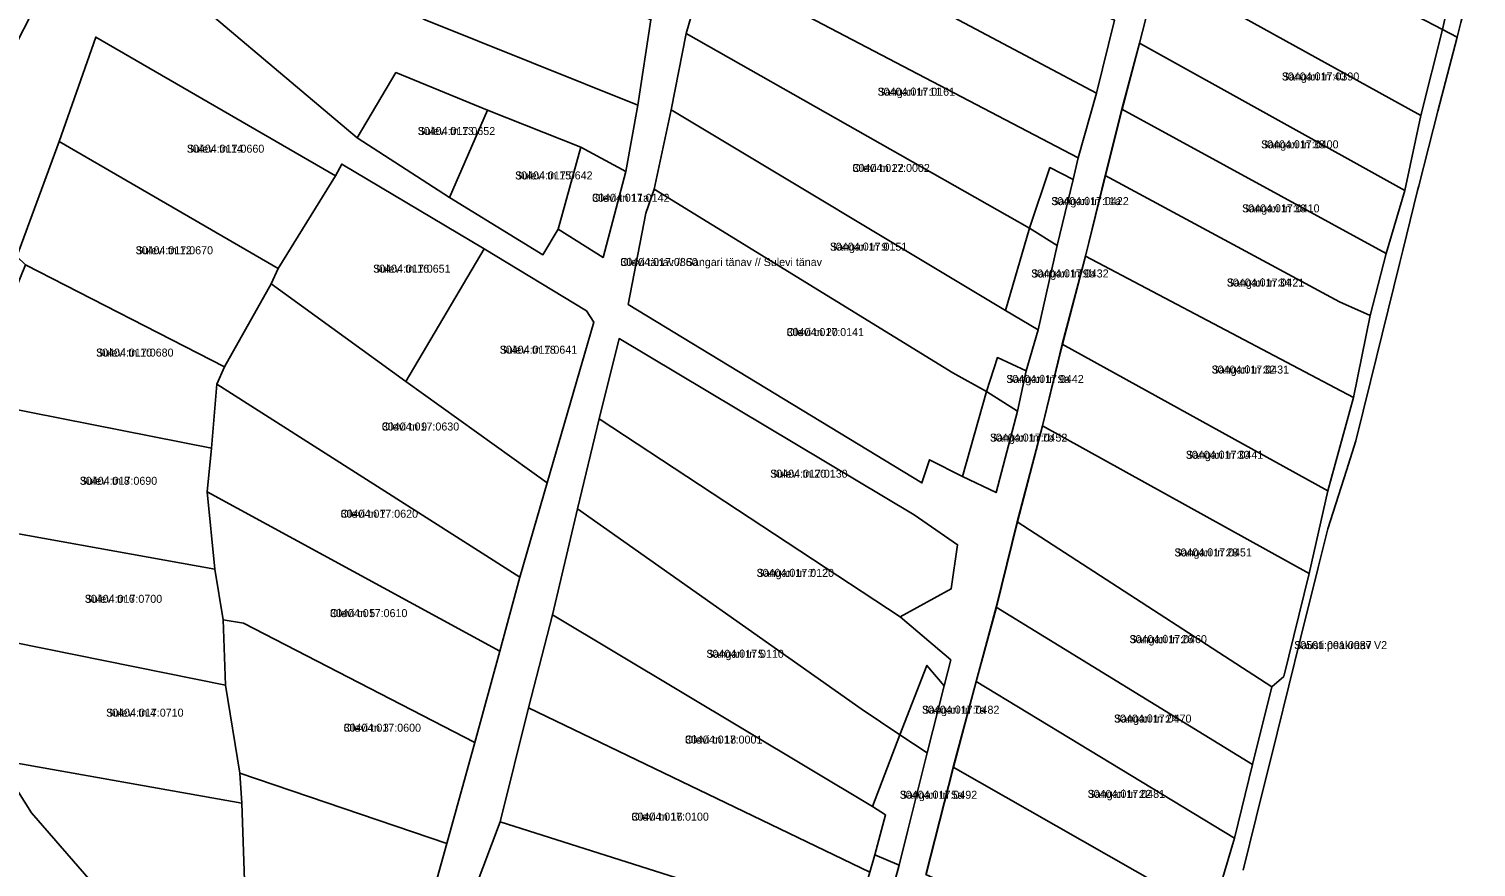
# Model space of a CAD drawing. Extents: x 542681 to 554572, y 6566489 to 6580482.
# Drawn here: x 544141.3 to 544412.6, y 6575830.3 to 6575987.4 of the extents above; entities that cross this region are included whole.
import ezdxf

# ---------------------------------------------------------------- set-up
doc = ezdxf.new("R2010")
doc.units = 0
for name, color, linetype in [('L_AADRESS', 7, 'Continuous'), ('PIIR', 7, 'Continuous'), ('TUNNUS', 7, 'Continuous')]:
    doc.layers.add(name, color=color, linetype=linetype)

msp = doc.modelspace()

# ---------------------------------------------------------------- linework, layer by layer
at = {"layer": 'PIIR'}
for points in [[(544132.71, 6575972.4), (544147.93, 6576002.3), (544147.47, 6576005.67), (544162.57, 6576001.02), (544202.83, 6575966.95), (544220.16, 6575955.78), (544237.67, 6575945.07), (544240.53, 6575949.86), (544248.94, 6575944.56), (544253.22, 6575960.63), (544255.42, 6575973.07), (544257.89, 6575989.06), (544259.46, 6576004.22), (544262.15, 6576022.75), (544264.4, 6576039.1), (544269.25, 6576064.08), (544276.88, 6576081.78), (544276.23, 6576102.8), (544232.03, 6576141.72), (544233.74, 6576145.65), (544276.06, 6576107.08), (544280.65, 6576140.9), (544291.75, 6576177.06)], [(544381.29, 6576166.31), (544393.77, 6576159.4), (544388.82, 6576138.6), (544384.78, 6576123.23), (544380.38, 6576105.94), (544376.63, 6576091.46), (544373.49, 6576078.95), (544370.21, 6576066.27), (544367.09, 6576054.03), (544363.21, 6576038.91), (544359.68, 6576024.81), (544356.57, 6576013.09), (544353, 6575998.36), (544349.5, 6575984.69), (544346.24, 6575972.34), (544343.11, 6575959.91), (544339.38, 6575944.78), (544335.04, 6575928.31), (544331.32, 6575913.02), (544326.6, 6575895.05), (544322.67, 6575879.05), (544318.89, 6575865.14), (544314.59, 6575849.07), (544309.48, 6575828.97)], [(544268.29, 6575999.66), (544264.52, 6575986.52), (544261.72, 6575972.19), (544258.49, 6575957.33), (544256.94, 6575952.84), (544253.66, 6575935.75), (544308.69, 6575902.31), (544310.14, 6575906.66), (544316.31, 6575903.53), (544322.6, 6575900.5), (544326.58, 6575915.74), (544328.21, 6575923.34), (544330.47, 6575931), (544334.01, 6575946.8), (544337.03, 6575959.16), (544337.96, 6575963.2), (544341.42, 6575975.31), (544344.79, 6575988.99)], [(544363.04, 6575821.48), (544367.27, 6575835.78), (544370.64, 6575849.55), (544374.28, 6575864.08), (544376.53, 6575866.05), (544381.27, 6575885.35), (544384.74, 6575900.84), (544389.59, 6575918.31), (544392.71, 6575933.67), (544395.69, 6575945.3), (544399.2, 6575957.07), (544402.23, 6575971.12), (544406.24, 6575987.27), (544409, 6575985.84), (544405.41, 6575971.95), (544403.63, 6575965.06), (544401.8, 6575957.99), (544401.56, 6575957.07), (544398.8, 6575945.86), (544398.24, 6575943.58), (544392.78, 6575921.34), (544390.04, 6575910.2), (544388.24, 6575904.61), (544384.75, 6575893.74), (544382.95, 6575886.48), (544379.65, 6575873.14), (544375.27, 6575855.46), (544371.34, 6575839.62), (544368.9, 6575829.76)], [(544368.9, 6575829.76), (544371.34, 6575839.62), (544375.27, 6575855.46), (544379.65, 6575873.14), (544382.95, 6575886.48), (544384.75, 6575893.74), (544388.24, 6575904.61), (544390.04, 6575910.2), (544392.78, 6575921.34), (544398.24, 6575943.58), (544398.8, 6575945.86), (544401.56, 6575957.07), (544401.8, 6575957.99), (544403.63, 6575965.06), (544405.41, 6575971.95), (544409, 6575985.84), (544409.71, 6575988.58)], [(544209.01, 6575796.68), (544219.68, 6575834.73), (544224.92, 6575853.69), (544229.59, 6575870.78), (544233.34, 6575884.68), (544238.44, 6575902.3), (544247.19, 6575932.44), (544245.8, 6575934.54), (544226.63, 6575946.16), (544199.95, 6575962.06), (544198.79, 6575959.82), (544153.86, 6575985.85), (544146.98, 6575966.27), (544139.03, 6575944.72), (544140.69, 6575943.15), (544130.3, 6575917.75), (544125.43, 6575895.3), (544125.04, 6575889.43), (544127.11, 6575874.75), (544128.58, 6575868.91), (544135.53, 6575850.42), (544141.79, 6575840.51), (544155.07, 6575825.29)], [(544300.11, 6575815.01), (544304.43, 6575830.67), (544306.07, 6575837.25), (544309.67, 6575851.73), (544312.89, 6575864.3), (544314.14, 6575869.14), (544304.61, 6575877.24), (544314.19, 6575882.46), (544315.37, 6575890.74), (544307.21, 6575896.36), (544251.95, 6575929.34), (544248.19, 6575914.3), (544244.17, 6575897.43), (544239.46, 6575877.59), (544234.93, 6575860.18), (544229.65, 6575838.82), (544221.69, 6575817.77)]]:
    msp.add_lwpolyline(points, dxfattribs=at)
for points in [[(544177.07, 6576030.33), (544257.89, 6575989.06), (544255.42, 6575973.07), (544215.56, 6575989.04), (544169.12, 6576014.32)], [(544268.31, 6576027.25), (544273.43, 6576024.32), (544291.56, 6576014.86), (544327.96, 6575996.68), (544344.79, 6575988.99), (544341.42, 6575975.31), (544270.37, 6576013.07)], [(544356.57, 6576013.09), (544359.63, 6576024.8), (544409.31, 6576001.08), (544406.24, 6575987.27)], [(544215.56, 6575989.04), (544255.42, 6575973.07), (544253.22, 6575960.63), (544244.77, 6575965.24), (544227.3, 6575972.12), (544210.1, 6575979.19), (544202.83, 6575966.95), (544162.57, 6576001.02), (544169.12, 6576014.32)], [(544270.37, 6576013.07), (544341.42, 6575975.31), (544337.96, 6575963.2), (544268.29, 6575999.66)], [(544352.95, 6575998.35), (544356.57, 6576013.09), (544406.24, 6575987.27), (544402.23, 6575971.12)], [(544406.24, 6575987.27), (544409.31, 6576001.08), (544412.55, 6575999.54), (544409.71, 6575988.58), (544409, 6575985.84)], [(544337.96, 6575963.2), (544337.03, 6575959.16), (544332.67, 6575961.4), (544328.86, 6575950.04), (544264.52, 6575986.52), (544268.29, 6575999.66)], [(544349.45, 6575984.68), (544352.95, 6575998.35), (544402.23, 6575971.12), (544399.2, 6575957.07)], [(544153.86, 6575985.85), (544198.79, 6575959.82), (544188.06, 6575942.5), (544146.98, 6575966.27)], [(544264.52, 6575986.52), (544328.86, 6575950.04), (544324.35, 6575934.63), (544261.72, 6575972.19)], [(544346.19, 6575972.33), (544349.45, 6575984.68), (544399.2, 6575957.07), (544395.69, 6575945.3)], [(544210.1, 6575979.19), (544227.3, 6575972.12), (544220.16, 6575955.78), (544202.83, 6575966.95)], [(544227.3, 6575972.12), (544244.77, 6575965.24), (544240.53, 6575949.86), (544237.67, 6575945.07), (544220.16, 6575955.78)], [(544261.72, 6575972.19), (544324.35, 6575934.63), (544330.47, 6575931), (544328.21, 6575923.34), (544322.83, 6575925.78), (544320.82, 6575919.44), (544314.48, 6575922.92), (544258.49, 6575957.33)], [(544343.06, 6575959.9), (544346.19, 6575972.33), (544395.69, 6575945.3), (544392.71, 6575933.67), (544386.94, 6575936.23)], [(544139.03, 6575944.72), (544146.98, 6575966.27), (544188.06, 6575942.5), (544186.73, 6575939.59), (544177.98, 6575924.04), (544140.69, 6575943.15)], [(544253.22, 6575960.63), (544248.94, 6575944.56), (544240.53, 6575949.86), (544244.77, 6575965.24)], [(544188.06, 6575942.5), (544198.79, 6575959.82), (544199.95, 6575962.06), (544226.63, 6575946.16), (544211.98, 6575921.34), (544186.73, 6575939.59)], [(544328.86, 6575950.04), (544332.67, 6575961.4), (544337.03, 6575959.16), (544334.01, 6575946.8)], [(544339.33, 6575944.77), (544343.06, 6575959.9), (544386.94, 6575936.23), (544392.71, 6575933.67), (544389.59, 6575918.31)], [(544314.48, 6575922.92), (544320.82, 6575919.44), (544316.31, 6575903.53), (544310.14, 6575906.66), (544308.69, 6575902.31), (544253.66, 6575935.75), (544256.94, 6575952.84), (544258.49, 6575957.33)], [(544324.35, 6575934.63), (544328.86, 6575950.04), (544334.01, 6575946.8), (544330.47, 6575931)], [(544226.63, 6575946.16), (544245.8, 6575934.54), (544247.19, 6575932.44), (544238.44, 6575902.3), (544211.98, 6575921.34)], [(544334.99, 6575928.3), (544339.33, 6575944.77), (544389.59, 6575918.31), (544384.74, 6575900.84)], [(544140.69, 6575943.15), (544177.98, 6575924.04), (544176.53, 6575920.81), (544175.57, 6575908.81), (544130.3, 6575917.75)], [(544177.98, 6575924.04), (544186.73, 6575939.59), (544211.98, 6575921.34), (544238.44, 6575902.3), (544233.34, 6575884.68), (544176.53, 6575920.81)], [(544251.95, 6575929.34), (544307.21, 6575896.36), (544315.37, 6575890.74), (544314.19, 6575882.46), (544304.61, 6575877.24), (544248.19, 6575914.3)], [(544331.27, 6575913.01), (544334.99, 6575928.3), (544384.74, 6575900.84), (544381.27, 6575885.35)], [(544322.83, 6575925.78), (544328.21, 6575923.34), (544326.58, 6575915.74), (544320.82, 6575919.44)], [(544175.57, 6575908.81), (544176.53, 6575920.81), (544233.34, 6575884.68), (544229.59, 6575870.78), (544174.74, 6575900.64)], [(544320.82, 6575919.44), (544326.58, 6575915.74), (544322.6, 6575900.5), (544316.31, 6575903.53)], [(544130.3, 6575917.75), (544175.57, 6575908.81), (544174.74, 6575900.64), (544176.16, 6575886.17), (544125.43, 6575895.3)], [(544248.19, 6575914.3), (544304.61, 6575877.24), (544314.14, 6575869.14), (544312.89, 6575864.3), (544309.63, 6575868.12), (544304.53, 6575855.13), (544297.33, 6575859.98), (544244.17, 6575897.43)], [(544326.55, 6575895.04), (544331.27, 6575913.01), (544381.27, 6575885.35), (544376.53, 6575866.05), (544374.28, 6575864.08)], [(544177.75, 6575876.67), (544176.16, 6575886.17), (544174.74, 6575900.64), (544229.59, 6575870.78), (544224.92, 6575853.69), (544181.57, 6575876.03)], [(544297.33, 6575859.98), (544304.53, 6575855.13), (544299.44, 6575841.68), (544239.46, 6575877.59), (544244.17, 6575897.43)], [(544125.04, 6575889.43), (544125.43, 6575895.3), (544176.16, 6575886.17), (544177.75, 6575876.67), (544178.16, 6575864.4), (544127.11, 6575874.75)], [(544322.62, 6575879.04), (544326.55, 6575895.04), (544374.28, 6575864.08), (544370.64, 6575849.55)], [(544318.84, 6575865.13), (544322.62, 6575879.04), (544370.64, 6575849.55), (544367.27, 6575835.78)], [(544178.16, 6575864.4), (544177.75, 6575876.67), (544181.57, 6575876.03), (544224.92, 6575853.69), (544219.68, 6575834.73), (544180.88, 6575847.95)], [(544299.44, 6575841.68), (544301.87, 6575840.16), (544299.88, 6575832.62), (544298.91, 6575829.36), (544234.93, 6575860.18), (544239.46, 6575877.59)], [(544128.58, 6575868.91), (544127.11, 6575874.75), (544178.16, 6575864.4), (544180.88, 6575847.95), (544181.25, 6575842.29), (544135.53, 6575850.42)], [(544309.63, 6575868.12), (544312.89, 6575864.3), (544309.67, 6575851.73), (544304.53, 6575855.13)], [(544314.54, 6575849.06), (544318.84, 6575865.13), (544367.27, 6575835.78), (544363.04, 6575821.48)], [(544298.91, 6575829.36), (544295.54, 6575817.9), (544229.65, 6575838.82), (544234.93, 6575860.18)], [(544309.67, 6575851.73), (544306.07, 6575837.25), (544304.43, 6575830.67), (544299.88, 6575832.62), (544301.87, 6575840.16), (544299.44, 6575841.68), (544304.53, 6575855.13)], [(544141.79, 6575840.51), (544135.53, 6575850.42), (544181.25, 6575842.29), (544182.58, 6575802.43), (544177.26, 6575800.27), (544155.07, 6575825.29)], [(544309.44, 6575828.96), (544314.54, 6575849.06), (544363.04, 6575821.48), (544359.27, 6575806.42)], [(544219.68, 6575834.73), (544209.01, 6575796.68), (544205.84, 6575785.06), (544187.11, 6575792.7), (544185.85, 6575801.7), (544182.58, 6575802.43), (544181.25, 6575842.29), (544180.88, 6575847.95)], [(544229.65, 6575838.82), (544295.54, 6575817.9), (544290.99, 6575800.42), (544221.69, 6575817.77)], [(544304.43, 6575830.67), (544300.06, 6575815), (544295.54, 6575817.9), (544298.91, 6575829.36), (544299.88, 6575832.62)]]:
    msp.add_lwpolyline(points, close=True, dxfattribs=at)

# ---------------------------------------------------------------- texts
at = {"layer": 'L_AADRESS'}
for s, p in [('Sangari tn 40', (544376.16, 6575977.71)), ('Sangari tn 11', (544300.4, 6575974.85)), ('Sulevi tn 13', (544214.21, 6575967.49)), ('Sulevi tn 14', (544170.94, 6575964.18)), ('Sangari tn 38', (544372.28, 6575964.99)), ('Olevi tn 22', (544295.68, 6575960.57)), ('Sulevi tn 15', (544232.46, 6575959.17)), ('Olevi tn 11a', (544246.88, 6575954.98)), ('Sangari tn 11a', (544332.95, 6575954.36)), ('Sangari tn 36', (544368.72, 6575953)), ('Sulevi tn 12', (544161.33, 6575945.15)), ('Sangari tn 9', (544291.46, 6575945.82)), ('Sulevi tn 16', (544205.85, 6575941.7)), ('Olevi tänav // Sangari tänav // Sulevi tänav', (544252.17, 6575942.95)), ('Sangari tn 9b', (544329.18, 6575940.8)), ('Sangari tn 34', (544365.85, 6575939.1)), ('Olevi tn 20', (544283.34, 6575929.82)), ('Sulevi tn 10', (544153.93, 6575925.98)), ('Sulevi tn 18', (544229.58, 6575926.52)), ('Sangari tn 32', (544363, 6575922.8)), ('Sangari tn 9a', (544324.52, 6575921.04)), ('Olevi tn 9', (544207.47, 6575912.13)), ('Sangari tn 7b', (544321.45, 6575910.05)), ('Sangari tn 30', (544358.17, 6575906.83)), ('Sulevi tn 8', (544150.87, 6575901.96)), ('Sulevi tn 20', (544280.27, 6575903.29)), ('Olevi tn 7', (544199.75, 6575895.79)), ('Sangari tn 28', (544356.03, 6575888.54)), ('Sangari tn 7', (544277.72, 6575884.71)), ('Sulevi tn 6', (544151.8, 6575879.85)), ('Olevi tn 5', (544197.76, 6575877.17)), ('Sangari tn 26', (544347.61, 6575872.29)), ('Sausti peakraav V2', (544378.48, 6575871.18)), ('Sangari tn 5', (544268.31, 6575869.55)), ('Sulevi tn 4', (544155.81, 6575858.52)), ('Sangari tn 7a', (544308.71, 6575859.07)), ('Olevi tn 3', (544200.31, 6575855.7)), ('Sangari tn 24', (544344.71, 6575857.41)), ('Olevi tn 18', (544264.29, 6575853.48)), ('Sangari tn 5a', (544304.55, 6575843.14)), ('Sangari tn 22', (544339.76, 6575843.3)), ('Olevi tn 16', (544254.26, 6575839.04))]:
    msp.add_text(s, height=1.5, dxfattribs=at).set_placement(p)
at = {"layer": 'TUNNUS'}
for s, p in [('30404:017:0390', (544376.16, 6575977.71)), ('30404:017:0161', (544300.4, 6575974.85)), ('30404:017:0652', (544214.21, 6575967.49)), ('30404:017:0660', (544170.94, 6575964.18)), ('30404:017:0400', (544372.28, 6575964.99)), ('30404:017:0642', (544232.46, 6575959.17)), ('30404:017:0002', (544295.68, 6575960.57)), ('30404:017:0142', (544246.88, 6575954.98)), ('30404:017:0422', (544332.95, 6575954.36)), ('30404:017:0410', (544368.72, 6575953)), ('30404:017:0670', (544161.33, 6575945.15)), ('30404:017:0151', (544291.46, 6575945.82)), ('30404:017:0651', (544205.85, 6575941.7)), ('30404:017:0860', (544252.17, 6575942.95)), ('30404:017:0432', (544329.18, 6575940.8)), ('30404:017:0421', (544365.85, 6575939.1)), ('30404:017:0141', (544283.34, 6575929.82)), ('30404:017:0680', (544153.93, 6575925.98)), ('30404:017:0641', (544229.58, 6575926.52)), ('30404:017:0431', (544363, 6575922.8)), ('30404:017:0442', (544324.52, 6575921.04)), ('30404:017:0630', (544207.47, 6575912.13)), ('30404:017:0452', (544321.45, 6575910.05)), ('30404:017:0441', (544358.17, 6575906.83)), ('30404:017:0690', (544150.87, 6575901.96)), ('30404:017:0130', (544280.27, 6575903.29)), ('30404:017:0620', (544199.75, 6575895.79)), ('30404:017:0451', (544356.03, 6575888.54)), ('30404:017:0120', (544277.72, 6575884.71)), ('30404:017:0700', (544151.8, 6575879.85)), ('30404:017:0610', (544197.76, 6575877.17)), ('30404:017:0460', (544347.61, 6575872.29)), ('30501:001:0087', (544378.48, 6575871.18)), ('30404:017:0110', (544268.31, 6575869.55)), ('30404:017:0710', (544155.81, 6575858.52)), ('30404:017:0482', (544308.71, 6575859.07)), ('30404:017:0600', (544200.31, 6575855.7)), ('30404:017:0470', (544344.71, 6575857.41)), ('30404:017:0001', (544264.29, 6575853.48)), ('30404:017:0492', (544304.55, 6575843.14)), ('30404:017:0481', (544339.76, 6575843.3)), ('30404:017:0100', (544254.26, 6575839.04))]:
    msp.add_text(s, height=1.5, dxfattribs=at).set_placement(p)

doc.saveas('drawing.dxf')
